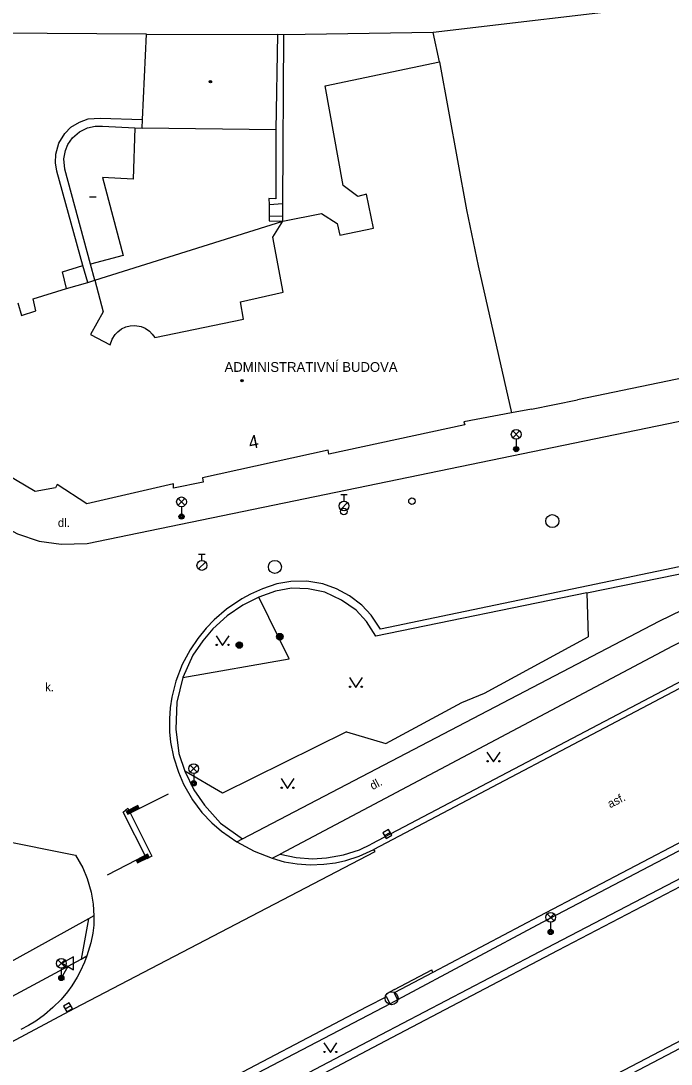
# Model space of a CAD drawing. Extents: x -598341 to -594502, y -1162301 to -1161406.
# Drawn here: x -597935 to -597885.1, y -1161870.5 to -1161790.5 of the extents above; entities that cross this region are included whole.
import ezdxf

# ---------------------------------------------------------------- set-up
doc = ezdxf.new("R2010")
doc.units = 0
for name, color, linetype in [('Vrstva 10', 7, 'Continuous'), ('Vrstva 11', 7, 'Continuous'), ('Vrstva 25', 7, 'Continuous'), ('Vrstva 27', 7, 'Continuous'), ('Vrstva 28', 7, 'Continuous'), ('Vrstva 33', 7, 'Continuous'), ('Vrstva 34', 7, 'Continuous'), ('Vrstva 36', 7, 'Continuous'), ('Vrstva 39', 7, 'Continuous'), ('Vrstva 40', 7, 'Continuous'), ('Vrstva 41', 7, 'Continuous'), ('Vrstva 46', 7, 'Continuous'), ('Vrstva 5', 7, 'Continuous'), ('Vrstva 7', 7, 'Continuous'), ('Vrstva 8', 7, 'Continuous'), ('Vrstva 9', 7, 'Continuous')]:
    doc.layers.add(name, color=color, linetype=linetype)

msp = doc.modelspace()

# ---------------------------------------------------------------- linework, layer by layer
at = {"layer": 'Vrstva 10'}
msp.add_line((-597938.69, -1161852.87), (-597930.8, -1161854.45), dxfattribs=at)
for points in [[(-597929.91, -1161830.55), (-597878.27, -1161819.9)], [(-597845.98, -1161822.91), (-597883.58, -1161841.19), (-597907.92, -1161854)], [(-597940.99, -1161823.85), (-597940.07, -1161825.63), (-597939.37, -1161826.61), (-597938.16, -1161827.94), (-597936.59, -1161829.09), (-597935.24, -1161829.81), (-597933.59, -1161830.37), (-597931.89, -1161830.61), (-597929.91, -1161830.55)], [(-597824.93, -1161824.97), (-597833.62, -1161828.78), (-597841.62, -1161832.43), (-597855.95, -1161839.15), (-597867.84, -1161844.95), (-597880.46, -1161851.38), (-597895.27, -1161859.13), (-597903.39, -1161863.43)], [(-597823.94, -1161827.8), (-597832.38, -1161831.5), (-597840.42, -1161835.17), (-597854.76, -1161841.92), (-597866.6, -1161847.72), (-597879.13, -1161854.09), (-597893.83, -1161861.76), (-597907.06, -1161868.69), (-597919.77, -1161875.39), (-597928.69, -1161880.09), (-597944.15, -1161888.2), (-597958.48, -1161895.69), (-597970.1, -1161901.86)], [(-597883.3, -1161832.09), (-597907.41, -1161837.11)], [(-597907.41, -1161837.11), (-597908.13, -1161836.04), (-597908.85, -1161835.27), (-597909.79, -1161834.55), (-597910.79, -1161834.02), (-597911.84, -1161833.65), (-597913.07, -1161833.44), (-597914.28, -1161833.45), (-597915.36, -1161833.64), (-597916.46, -1161834.01), (-597917.39, -1161834.44), (-597918.05, -1161834.8), (-597919.22, -1161835.59), (-597920.16, -1161836.41), (-597920.78, -1161837.04), (-597921.41, -1161837.82), (-597922.01, -1161838.7), (-597922.61, -1161839.83), (-597923.11, -1161841.1), (-597923.41, -1161842.34), (-597923.54, -1161843.15), (-597923.6, -1161843.99), (-597923.59, -1161844.98), (-597923.51, -1161845.79), (-597923.28, -1161846.91), (-597922.91, -1161848.07), (-597922.51, -1161849.01), (-597921.84, -1161850.2), (-597921.11, -1161851.16), (-597920.35, -1161851.95), (-597919.61, -1161852.61), (-597918.43, -1161853.41)], [(-597918.43, -1161853.41), (-597917.11, -1161854.13), (-597915.71, -1161854.68)], [(-597915.71, -1161854.68), (-597914.79, -1161854.94), (-597913.8, -1161855.11), (-597912.81, -1161855.18), (-597911.75, -1161855.14), (-597910.86, -1161855.03), (-597910.08, -1161854.86), (-597909.06, -1161854.53), (-597907.92, -1161854)], [(-597930.8, -1161854.45), (-597930.25, -1161855.4), (-597929.91, -1161856.23), (-597929.6, -1161857.28), (-597929.45, -1161858.21), (-597929.4, -1161859.09)], [(-597929.4, -1161859.09), (-597929.4, -1161859.8), (-597929.47, -1161860.42), (-597929.63, -1161861.16), (-597929.93, -1161862.17)], [(-597929.93, -1161862.17), (-597930.11, -1161862.65), (-597930.45, -1161863.36), (-597930.68, -1161863.8), (-597931.09, -1161864.46), (-597931.41, -1161864.92), (-597931.9, -1161865.5), (-597932.53, -1161866.13), (-597933.17, -1161866.68), (-597933.83, -1161867.16), (-597934.4, -1161867.51), (-597935, -1161867.81)], [(-597873.15, -1161862.76), (-597890.99, -1161872.11), (-597897.54, -1161875.64)], [(-597903.39, -1161863.43), (-597906.37, -1161865), (-597906.11, -1161865.54)], [(-597906.67, -1161865.85), (-597906.96, -1161865.31), (-597908.45, -1161866.07), (-597921.02, -1161872.66), (-597930.21, -1161877.5), (-597945.43, -1161885.47), (-597959.97, -1161893.12), (-597971.26, -1161899.06)], [(-597906.11, -1161865.54), (-597906.67, -1161865.85)]]:
    msp.add_lwpolyline(points, dxfattribs=at)
at = {"layer": 'Vrstva 11'}
for p, q in [((-597885.98, -1161789.33), (-597903.38, -1161791.36)), ((-597925.35, -1161791.5), (-597947.16, -1161791.33)), ((-597914.83, -1161791.54), (-597915.32, -1161791.52)), ((-597914.9, -1161804.47), (-597914.83, -1161791.54)), ((-597903.38, -1161791.36), (-597914.83, -1161791.54)), ((-597902.9, -1161793.61), (-597903.38, -1161791.36)), ((-597928.91, -1161797.93), (-597925.67, -1161798.04)), ((-597926.26, -1161798.69), (-597925.69, -1161798.71)), ((-597930.25, -1161809.24), (-597932.22, -1161801.99)), ((-597915.95, -1161804.57), (-597914.9, -1161804.47)), ((-597915.95, -1161804.57), (-597915.94, -1161805.44)), ((-597914.91, -1161805.43), (-597914.9, -1161804.47)), ((-597915.94, -1161805.44), (-597914.91, -1161805.43)), ((-597914.9, -1161805.83), (-597914.91, -1161805.43)), ((-597929.33, -1161810.36), (-597914.9, -1161805.83)), ((-597929.85, -1161810.54), (-597930.25, -1161809.24)), ((-597929.33, -1161810.36), (-597929.65, -1161809.14)), ((-597891.6, -1161834.34), (-597882.89, -1161832.55)), ((-597891.6, -1161834.34), (-597907.76, -1161837.64)), ((-597891.6, -1161834.34), (-597891.48, -1161837.7)), ((-597914.43, -1161839.39), (-597916.75, -1161834.66)), ((-597899.44, -1161842.02), (-597891.48, -1161837.7)), ((-597922.56, -1161840.83), (-597914.43, -1161839.39)), ((-597901.18, -1161842.73), (-597899.44, -1161842.02)), ((-597910.01, -1161844.98), (-597919.54, -1161849.7)), ((-597919.54, -1161849.7), (-597922.42, -1161848)), ((-597915.71, -1161854.68), (-597915.11, -1161854.36)), ((-597929.8, -1161859.31), (-597930.37, -1161862.41)), ((-597903.39, -1161863.43), (-597903.48, -1161863.24)), ((-597906.35, -1161864.75), (-597906.95, -1161865.06))]:
    msp.add_line(p, q, dxfattribs=at)
for points in [[(-597932.22, -1161801.99), (-597932.34, -1161801.37), (-597932.31, -1161800.71), (-597932.07, -1161799.86), (-597931.61, -1161799.11), (-597931.15, -1161798.64), (-597930.5, -1161798.24), (-597929.82, -1161797.99), (-597928.91, -1161797.93)], [(-597915.43, -1161798.83), (-597915.43, -1161804.12), (-597915.98, -1161804.1), (-597915.95, -1161804.57)], [(-597915.94, -1161805.44), (-597915.96, -1161805.82), (-597914.9, -1161805.83)], [(-597931.49, -1161810.99), (-597931.8, -1161809.71), (-597930.25, -1161809.24)], [(-597918, -1161853.19), (-597886.06, -1161836.49), (-597844.3, -1161816.24)], [(-597846.12, -1161822.47), (-597847.16, -1161819.96), (-597885.02, -1161838.43), (-597915.11, -1161854.36)], [(-597846.12, -1161822.47), (-597883.78, -1161840.79), (-597908.13, -1161853.6)], [(-597824.72, -1161825.45), (-597833.3, -1161829.27), (-597841.4, -1161832.91), (-597855.72, -1161839.63), (-597867.6, -1161845.42), (-597880.22, -1161851.85), (-597895.02, -1161859.6), (-597906.11, -1161865.54)], [(-597824.19, -1161827.2), (-597832.61, -1161830.99), (-597840.65, -1161834.67), (-597855, -1161841.42), (-597866.85, -1161847.22), (-597879.38, -1161853.6), (-597894.09, -1161861.27), (-597907.4, -1161868.22)], [(-597907.76, -1161837.64), (-597908.49, -1161836.53), (-597909.29, -1161835.66), (-597910.4, -1161834.88), (-597911.68, -1161834.29), (-597912.95, -1161834.03), (-597914.24, -1161833.98), (-597915.47, -1161834.2), (-597916.75, -1161834.66)], [(-597916.75, -1161834.66), (-597917.98, -1161835.27), (-597919.16, -1161836.09), (-597920.28, -1161837.1), (-597921.03, -1161838), (-597921.81, -1161839.12), (-597922.56, -1161840.83)], [(-597922.56, -1161840.83), (-597923.02, -1161842.72), (-597923.11, -1161844.77), (-597922.87, -1161846.64), (-597922.42, -1161848)], [(-597910.01, -1161844.98), (-597907, -1161845.87), (-597901.18, -1161842.73)], [(-597922.42, -1161848), (-597921.74, -1161849.42), (-597920.92, -1161850.62), (-597919.69, -1161851.99), (-597918, -1161853.19)], [(-597925.34, -1161854.73), (-597927.14, -1161851.14), (-597926.79, -1161850.83), (-597924.94, -1161854.53), (-597925.34, -1161854.73)], [(-597918.43, -1161853.41), (-597918, -1161853.19)], [(-597930.91, -1161866.2), (-597907.83, -1161854.17), (-597907.92, -1161854)], [(-597915.11, -1161854.36), (-597913.88, -1161854.63), (-597912.64, -1161854.71), (-597911.55, -1161854.65), (-597910.26, -1161854.42), (-597909.03, -1161854.02), (-597908.13, -1161853.6)], [(-597929.4, -1161859.09), (-597929.8, -1161859.31)], [(-597929.8, -1161859.31), (-597945.12, -1161867.77)], [(-597930.37, -1161862.41), (-597929.93, -1161862.17)], [(-597944.62, -1161870.09), (-597930.37, -1161862.41)], [(-597906.35, -1161864.75), (-597903.48, -1161863.24)], [(-598022.53, -1161914.7), (-597995.76, -1161900.52), (-597990.72, -1161897.79), (-597968.63, -1161886.25), (-597946.23, -1161874.37), (-597930.91, -1161866.2)], [(-597906.67, -1161865.85), (-597920.8, -1161873.22), (-597929.91, -1161878.01), (-597945.23, -1161886.01), (-597959.66, -1161893.59), (-597971.1, -1161899.64)], [(-597907.4, -1161868.22), (-597920, -1161874.83), (-597928.97, -1161879.57), (-597944.32, -1161887.63), (-597958.82, -1161895.22), (-597970.32, -1161901.32)]]:
    msp.add_lwpolyline(points, dxfattribs=at)
at = {"layer": 'Vrstva 25'}
for centre, radius in [((-597915.14, -1161837.69), 0.25), ((-597915.14, -1161837.69), 0.2), ((-597915.14, -1161837.69), 0.15), ((-597915.14, -1161837.69), 0.1), ((-597918.24, -1161838.33), 0.25), ((-597918.24, -1161838.33), 0.2), ((-597918.24, -1161838.33), 0.15), ((-597918.24, -1161838.33), 0.1), ((-597918.24, -1161838.33), 0.05), ((-597915.14, -1161837.69), 0.05)]:
    msp.add_circle(centre, radius, dxfattribs=at)
at = {"layer": 'Vrstva 27'}
for p, q in [((-597907.109, -1161852.94), (-597906.671, -1161852.7)), ((-597931.587, -1161866.224), (-597931.153, -1161865.975))]:
    msp.add_line(p, q, dxfattribs=at)
for points in [[(-597906.989, -1161853.159), (-597906.551, -1161852.919), (-597906.791, -1161852.481), (-597907.229, -1161852.721)], [(-597931.462, -1161866.441), (-597931.028, -1161866.192), (-597931.277, -1161865.758), (-597931.711, -1161866.007)]]:
    msp.add_lwpolyline(points, close=True, dxfattribs=at)
for centre in [(-597894.24, -1161828.83), (-597915.51, -1161832.34), (-597906.56, -1161865.41)]:
    msp.add_circle(centre, 0.5, dxfattribs=at)
at = {"layer": 'Vrstva 28'}
for p, q in [((-597910.46, -1161826.795), (-597909.96, -1161826.795)), ((-597910.21, -1161827.295), (-597910.21, -1161826.795)), ((-597910.468, -1161827.942), (-597909.938, -1161827.412)), ((-597921.368, -1161832.502), (-597920.838, -1161831.972)), ((-597921.36, -1161831.355), (-597920.86, -1161831.355)), ((-597921.11, -1161831.855), (-597921.11, -1161831.355))]:
    msp.add_line(p, q, dxfattribs=at)
for centre, radius in [((-597905, -1161827.3), 0.25), ((-597910.21, -1161827.67), 0.375), ((-597910.23, -1161828.09), 0.25), ((-597921.11, -1161832.23), 0.375)]:
    msp.add_circle(centre, radius, dxfattribs=at)
at = {"layer": 'Vrstva 33'}
for p, q in [((-597897.275, -1161822.45), (-597896.745, -1161821.92)), ((-597897.275, -1161821.92), (-597896.745, -1161822.45)), ((-597897.01, -1161822.56), (-597897.01, -1161823.31)), ((-597922.935, -1161827.62), (-597922.405, -1161827.09)), ((-597922.935, -1161827.09), (-597922.405, -1161827.62)), ((-597922.67, -1161827.73), (-597922.67, -1161828.48)), ((-597922.005, -1161848.07), (-597921.475, -1161847.54)), ((-597922.005, -1161847.54), (-597921.475, -1161848.07)), ((-597921.74, -1161848.18), (-597921.74, -1161848.93)), ((-597925.907, -1161850.86), (-597923.675, -1161849.733)), ((-597926.159, -1161854.819), (-597928.38, -1161855.965)), ((-597894.635, -1161859.47), (-597894.105, -1161858.94)), ((-597894.635, -1161858.94), (-597894.105, -1161859.47)), ((-597894.37, -1161859.58), (-597894.37, -1161860.33)), ((-597932.155, -1161863), (-597931.625, -1161862.47)), ((-597932.155, -1161862.47), (-597931.625, -1161863)), ((-597931.89, -1161863.11), (-597931.89, -1161863.86))]:
    msp.add_line(p, q, dxfattribs=at)
for points in [[(-597926.8, -1161851.31), (-597925.907, -1161850.86), (-597926.02, -1161850.636), (-597926.913, -1161851.087)], [(-597926.778, -1161851.243), (-597925.974, -1161850.837), (-597926.042, -1161850.703), (-597926.845, -1161851.109)], [(-597926.756, -1161851.176), (-597926.042, -1161850.815), (-597926.064, -1161850.771), (-597926.778, -1161851.131)], [(-597925.27, -1161854.36), (-597926.159, -1161854.819), (-597926.044, -1161855.041), (-597925.155, -1161854.582)], [(-597925.292, -1161854.427), (-597926.091, -1161854.84), (-597926.023, -1161854.973), (-597925.223, -1161854.561)], [(-597925.313, -1161854.495), (-597926.024, -1161854.862), (-597926.001, -1161854.906), (-597925.29, -1161854.539)]]:
    msp.add_lwpolyline(points, close=True, dxfattribs=at)
for centre, radius in [((-597897.01, -1161822.185), 0.375), ((-597897.01, -1161823.31), 0.2), ((-597897.01, -1161823.31), 0.145), ((-597897.01, -1161823.31), 0.0876), ((-597922.67, -1161827.355), 0.375), ((-597922.67, -1161828.48), 0.2), ((-597922.67, -1161828.48), 0.145), ((-597922.67, -1161828.48), 0.0876), ((-597921.74, -1161847.805), 0.375), ((-597921.74, -1161848.93), 0.2), ((-597921.74, -1161848.93), 0.145), ((-597921.74, -1161848.93), 0.0876), ((-597894.37, -1161859.205), 0.375), ((-597894.37, -1161860.33), 0.2), ((-597894.37, -1161860.33), 0.145), ((-597894.37, -1161860.33), 0.0876), ((-597931.89, -1161862.735), 0.375), ((-597931.89, -1161863.86), 0.2), ((-597931.89, -1161863.86), 0.145), ((-597931.89, -1161863.86), 0.0876)]:
    msp.add_circle(centre, radius, dxfattribs=at)
at = {"layer": 'Vrstva 34'}
for p, q in [((-597931.381, -1161862.978), (-597931.89, -1161863.86)), ((-597932.107, -1161863.735), (-597931.673, -1161863.985))]:
    msp.add_line(p, q, dxfattribs=at)
msp.add_lwpolyline([(-597931.814, -1161862.728), (-597930.948, -1161863.228), (-597930.948, -1161862.228)], close=True, dxfattribs=at)
at = {"layer": 'Vrstva 36'}
for points in [[(-597920.02, -1161837.62), (-597919.52, -1161838.37), (-597919.02, -1161837.62)], [(-597909.8, -1161840.83), (-597909.3, -1161841.58), (-597908.8, -1161840.83)], [(-597899.25, -1161846.54), (-597898.75, -1161847.29), (-597898.25, -1161846.54)], [(-597915.04, -1161848.57), (-597914.54, -1161849.32), (-597914.04, -1161848.57)], [(-597911.76, -1161868.83), (-597911.26, -1161869.58), (-597910.76, -1161868.83)]]:
    msp.add_lwpolyline(points, dxfattribs=at)
for centre in [(-597919.97, -1161838.32), (-597919.071, -1161838.32), (-597909.75, -1161841.53), (-597908.851, -1161841.53), (-597899.2, -1161847.24), (-597898.3, -1161847.24), (-597914.99, -1161849.27), (-597914.091, -1161849.27), (-597911.71, -1161869.53), (-597910.811, -1161869.53)]:
    msp.add_circle(centre, 0.05, dxfattribs=at)
at = {"layer": 'Vrstva 39'}
msp.add_line((-597929.72, -1161803.98), (-597929.22, -1161803.98), dxfattribs=at)
for centre, radius in [((-597920.45, -1161795.14), 0.09), ((-597920.45, -1161795.14), 0.0398), ((-597918.03, -1161818.06), 0.09), ((-597918.03, -1161818.06), 0.0398)]:
    msp.add_circle(centre, radius, dxfattribs=at)
at = {"layer": 'Vrstva 5'}
for p, q in [((-597925.67, -1161798.04), (-597925.35, -1161791.5)), ((-597925.35, -1161791.5), (-597915.32, -1161791.52)), ((-597915.32, -1161791.52), (-597915.43, -1161798.83)), ((-597911.66, -1161795.45), (-597902.9, -1161793.61)), ((-597902.9, -1161793.61), (-597900.82, -1161804.97)), ((-597910.28, -1161803.1), (-597911.66, -1161795.45)), ((-597925.69, -1161798.71), (-597925.67, -1161798.04)), ((-597931.02, -1161799.44), (-597930.5, -1161798.98)), ((-597930.5, -1161798.98), (-597929.87, -1161798.68)), ((-597929.87, -1161798.68), (-597929.3, -1161798.55)), ((-597929.3, -1161798.55), (-597928.72, -1161798.55)), ((-597928.72, -1161798.55), (-597926.26, -1161798.69)), ((-597926.26, -1161798.69), (-597926.37, -1161802.61)), ((-597915.43, -1161798.83), (-597925.69, -1161798.71)), ((-597931.58, -1161800.43), (-597931.38, -1161799.95)), ((-597931.38, -1161799.95), (-597931.02, -1161799.44)), ((-597931.69, -1161801.06), (-597931.58, -1161800.43)), ((-597931.61, -1161801.84), (-597931.69, -1161801.06)), ((-597929.65, -1161809.14), (-597931.61, -1161801.84)), ((-597926.37, -1161802.61), (-597928.73, -1161802.5)), ((-597928.73, -1161802.5), (-597927.14, -1161808.47)), ((-597909.16, -1161803.94), (-597910.28, -1161803.1)), ((-597908.49, -1161803.76), (-597909.16, -1161803.94)), ((-597907.95, -1161806.38), (-597908.49, -1161803.76)), ((-597914.9, -1161805.83), (-597911.95, -1161805.24)), ((-597911.95, -1161805.24), (-597910.74, -1161806.02)), ((-597900.82, -1161804.97), (-597899.92, -1161809.25)), ((-597915.68, -1161807.06), (-597914.9, -1161805.83)), ((-597910.74, -1161806.02), (-597910.53, -1161806.92)), ((-597910.53, -1161806.92), (-597907.95, -1161806.38)), ((-597914.88, -1161811.29), (-597915.68, -1161807.06)), ((-597927.14, -1161808.47), (-597929.65, -1161809.14)), ((-597899.92, -1161809.25), (-597897.37, -1161820.53)), ((-597929.85, -1161810.54), (-597929.33, -1161810.36)), ((-597929.33, -1161810.36), (-597928.67, -1161812.78)), ((-597934.05, -1161811.8), (-597931.49, -1161810.99)), ((-597931.49, -1161810.99), (-597929.85, -1161810.54)), ((-597933.83, -1161812.7), (-597934.05, -1161811.8)), ((-597918.14, -1161812.03), (-597914.88, -1161811.29)), ((-597935.22, -1161812.1), (-597934.95, -1161813.07)), ((-597934.95, -1161813.07), (-597933.83, -1161812.7)), ((-597928.67, -1161812.78), (-597929.66, -1161814.52)), ((-597917.91, -1161813.35), (-597918.14, -1161812.03)), ((-597924.72, -1161814.76), (-597917.91, -1161813.35)), ((-597927.77, -1161814.53), (-597927.56, -1161814.31)), ((-597927.56, -1161814.31), (-597927.27, -1161814.09)), ((-597927.27, -1161814.09), (-597926.95, -1161813.94)), ((-597926.95, -1161813.94), (-597926.62, -1161813.86)), ((-597926.62, -1161813.86), (-597926.25, -1161813.83)), ((-597926.25, -1161813.83), (-597925.77, -1161813.92)), ((-597925.77, -1161813.92), (-597925.45, -1161814.05)), ((-597925.45, -1161814.05), (-597925.13, -1161814.26)), ((-597925.13, -1161814.26), (-597924.91, -1161814.49)), ((-597929.66, -1161814.52), (-597928.13, -1161815.32)), ((-597928.13, -1161815.32), (-597927.98, -1161814.87)), ((-597927.98, -1161814.87), (-597927.77, -1161814.53)), ((-597924.91, -1161814.49), (-597924.72, -1161814.76)), ((-597897.37, -1161820.53), (-597901.02, -1161821.22)), ((-597900.96, -1161821.45), (-597911.37, -1161823.71)), ((-597901.02, -1161821.22), (-597900.96, -1161821.45)), ((-597911.44, -1161823.4), (-597921.07, -1161825.52)), ((-597911.37, -1161823.71), (-597911.44, -1161823.4)), ((-597933.89, -1161826.56), (-597936.09, -1161825.26)), ((-597921.07, -1161825.52), (-597921, -1161825.84)), ((-597932.33, -1161826.28), (-597933.89, -1161826.56)), ((-597932.21, -1161826.02), (-597932.33, -1161826.28)), ((-597929.93, -1161827.5), (-597932.21, -1161826.02)), ((-597923.29, -1161825.97), (-597929.93, -1161827.5)), ((-597923.28, -1161826.31), (-597923.29, -1161825.97)), ((-597921, -1161825.84), (-597923.28, -1161826.31))]:
    msp.add_line(p, q, dxfattribs=at)
at = {"layer": 'Vrstva 7'}
for p, q in [((-597880.41, -1161817.05), (-597892.3, -1161819.54)), ((-597895.83, -1161820.26), (-597897.37, -1161820.53))]:
    msp.add_line(p, q, dxfattribs=at)
at = {"layer": 'Vrstva 8'}
msp.add_line((-597895.83, -1161820.26), (-597892.3, -1161819.54), dxfattribs=at)
at = {"layer": 'Vrstva 9'}
msp.add_lwpolyline([(-597872.92, -1161863.2), (-597890.75, -1161872.55), (-597897.31, -1161876.08), (-597907.21, -1161881.3), (-597913.9, -1161884.86)], dxfattribs=at)

# ---------------------------------------------------------------- texts
at = {"layer": 'Vrstva 40'}
for s, p in [('dl.', (-597932.15, -1161829.28)), ('k.', (-597933.13, -1161841.87))]:
    msp.add_text(s, height=0.65, dxfattribs=at).set_placement(p)
for s, rotation, p in [('dl.', 27.75713, (-597908.02, -1161849.46)), ('asf.', 26.73155, (-597889.81, -1161850.85))]:
    msp.add_text(s, height=0.6499, rotation=rotation, dxfattribs=at).set_placement(p)
at = {"layer": 'Vrstva 41'}
msp.add_text('ADMINISTRATIVNÍ BUDOVA', height=0.75, dxfattribs=at).set_placement((-597919.37, -1161817.39))
at = {"layer": 'Vrstva 46'}
msp.add_text('4', height=1, rotation=11.4, dxfattribs=at).set_placement((-597917.42, -1161823.32))

doc.saveas('drawing.dxf')
